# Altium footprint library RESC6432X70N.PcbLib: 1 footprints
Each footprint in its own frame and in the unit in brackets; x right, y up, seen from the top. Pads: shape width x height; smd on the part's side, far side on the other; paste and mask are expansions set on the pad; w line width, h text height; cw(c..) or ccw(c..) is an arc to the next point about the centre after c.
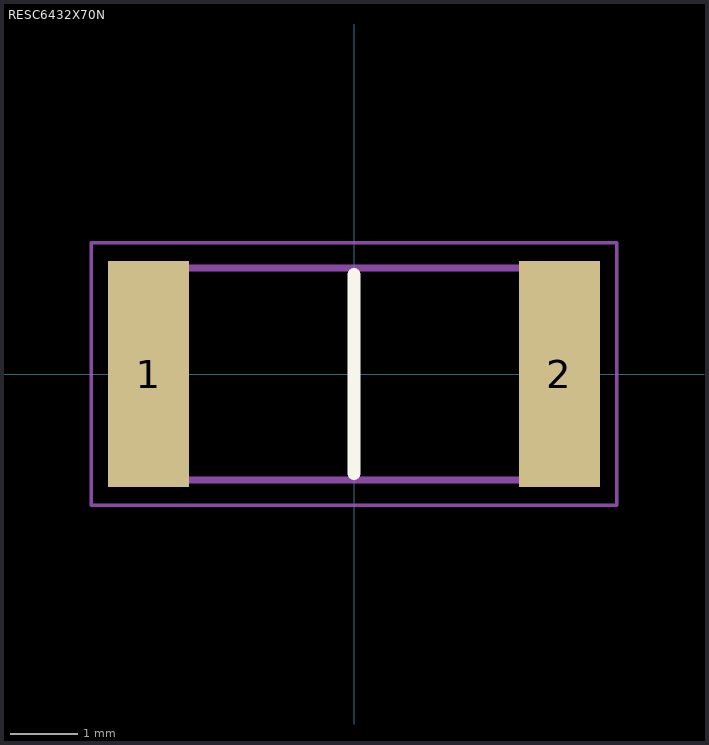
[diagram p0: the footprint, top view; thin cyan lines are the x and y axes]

## RESC6432X70N [mm]
pads (2):
  rect 1.2x3.35 smd: 1(-3.05,0) 2(3.05,0)
Top Overlay:
  lines w0.2: 0,-1.475 0,1.475
Mechanical 15:
  lines w0.1: -3.175,-1.575 3.175,-1.575 3.175,1.575 -3.175,1.575 -3.175,-1.575
Mechanical 20:
  lines w0.05: -3.9,-1.95 3.9,-1.95 3.9,1.95 -3.9,1.95 -3.9,-1.95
